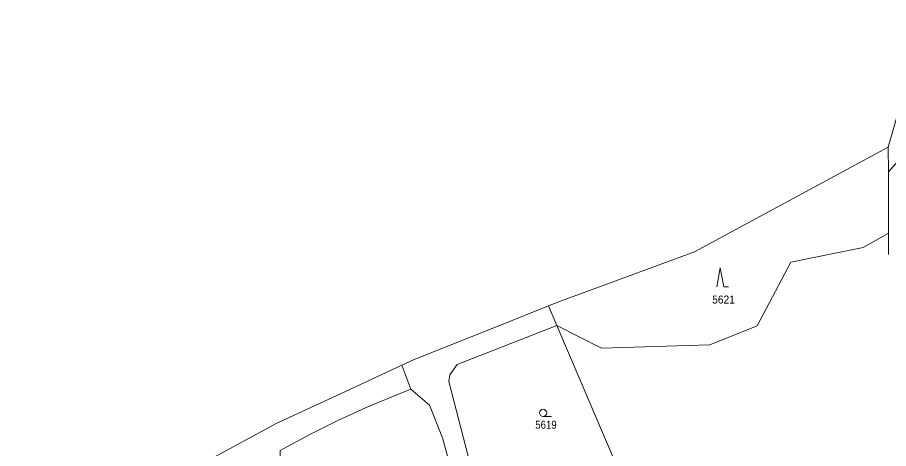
# Model space of a CAD drawing. Extents: x -590528 to -586543, y -1119609 to -1116685.
# Drawn here: x -588746.2 to -588561.2, y -1117717.3 to -1117625.7 of the extents above; entities that cross this region are included whole.
import ezdxf

# ---------------------------------------------------------------- set-up
doc = ezdxf.new("R2010")
doc.units = 0
doc.header["$LTSCALE"] = 0.68
for name, color, linetype, lineweight in [('1', 7, 'Continuous', 13), ('3', 7, 'Continuous', 13), ('6', 7, 'Continuous', 13)]:
    doc.layers.add(name, color=color, linetype=linetype, lineweight=lineweight)

msp = doc.modelspace()

# ---------------------------------------------------------------- linework, layer by layer
at = {"layer": '1'}
for p, q in [((-588561.27, -1117653.3), (-588561.26, -1117658.54)), ((-588602.44, -1117675.51), (-588630.88, -1117686)), ((-588631.65, -1117691.14), (-588633.41, -1117687.01)), ((-588643.57, -1117691.06), (-588661.91, -1117698.38)), ((-588662.62, -1117704.65), (-588664.54, -1117699.61))]:
    msp.add_line(p, q, dxfattribs=at)
for points in [[(-588553.37, -1117625.71), (-588561.27, -1117653.3), (-588602.44, -1117675.51)], [(-588548.03, -1117646.69), (-588553.62, -1117646.45), (-588555.38, -1117651.89), (-588561.26, -1117658.54), (-588561.22, -1117671.52), (-588561.21, -1117676.04)], [(-588561.22, -1117671.52), (-588566.59, -1117674.55), (-588582, -1117677.69), (-588589.08, -1117691.22)], [(-588630.88, -1117686), (-588633.41, -1117687.01), (-588643.57, -1117691.06)], [(-588631.65, -1117691.14), (-588652.8, -1117699.46), (-588654.35, -1117701.63), (-588654.54, -1117703.04), (-588645.67, -1117737.56), (-588643.08, -1117747.63), (-588640.63, -1117754.02)], [(-588645.67, -1117737.56), (-588616.38, -1117726.97), (-588631.65, -1117691.14)], [(-588589.08, -1117691.22), (-588599.15, -1117695.28), (-588622.15, -1117695.96), (-588631.65, -1117691.14)], [(-588661.91, -1117698.38), (-588664.54, -1117699.61), (-588676.52, -1117705.2), (-588691.07, -1117711.89), (-588746.16, -1117741.76)], [(-588662.62, -1117704.65), (-588666.31, -1117706.13), (-588672.27, -1117708.63), (-588678.15, -1117711.33), (-588683.93, -1117714.22), (-588689.61, -1117717.29), (-588690.36, -1117717.71), (-588690.6, -1117766.52)], [(-588641.48, -1117759.48), (-588646.61, -1117749.7), (-588649.93, -1117737.19), (-588655.92, -1117715.01), (-588658.71, -1117708.06), (-588662.62, -1117704.65)]]:
    msp.add_lwpolyline(points, dxfattribs=at)
at = {"layer": '6'}
msp.add_line((-588634.55, -1117710.46), (-588632.8, -1117710.46), dxfattribs=at)
msp.add_lwpolyline([(-588597.7, -1117682.92), (-588596.95, -1117678.92), (-588596.2, -1117682.92), (-588595.2, -1117682.92)], dxfattribs=at)
msp.add_circle((-588634.55, -1117709.71), 0.75, dxfattribs=at)

# ---------------------------------------------------------------- texts
at = {"layer": '3'}
for s, width, p in [('5621', 0.95, (-588598.653, -1117686.49)), ('5619', 0.9, (-588636.223, -1117713.08))]:
    msp.add_text(s, height=1.7, dxfattribs=dict(at, width=width)).set_placement(p)

doc.saveas('drawing.dxf')
